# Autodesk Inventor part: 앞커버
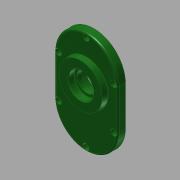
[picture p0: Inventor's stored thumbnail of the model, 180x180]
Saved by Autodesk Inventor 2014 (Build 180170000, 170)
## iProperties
Created: 2016-12
Part Number: 앞커버
Material: 일반
Document SubType Name: Modeling
Designer: mduedu
Density: 1 g/cm^3
Appearance: 매끄러움 - 짙은 산림 녹색
Mass: 97.7255 g
Surface Area: 264.104 cm^2
Volume: 97.7255 cm^3
Author: mduedu
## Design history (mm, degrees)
sketch "스케치1"
  geometry: L1 (40, -25)-(40, 25); L2 (-40, 25)-(-40, -25); L3 (-40, -25)-(40, 25); L4 (40, -25)-(-40, 25); A1 r 40 centre (0, 25) between (40, 25) and (-40, 25); A2 r 40 centre (0, -25) between (-40, -25) and (40, -25); 1 further point
  constraints: 8 end point, 4 point on circle, 4 tangent, 2 centre point, 2 midpoint, 1 parallel, 1 vertical
  dimensions: "d0" = 130 dimension on A2 A1; "d2" = 80 distance between parallel lines of L1 L2
extrude "돌출1" new body sketch "스케치1" distance "d3" = 10; taper "d4" = 0 deg
sketch "스케치2"
  geometry: C1 r 21 at (0, 11); 1 further point
  constraints: 1 centre point, 1 vertical alignment
  dimensions: "d5" = 42 diameter of C1; "d7" = 11 distance of C1.centre point (0, 0)
extrude "돌출2" join sketch "스케치2" distance "d8" = 7; taper "d9" = 0 deg
sketch "스케치3"
  geometry: C1 r 15 at (0, -33.1); C2 r 21 at (0, 11) reference; 1 further point
  constraints: 1 centre point, 1 vertical alignment
  dimensions: "d10" = 30 diameter of C1; "d71" = 44.1 distance of C1.centre C2.centre
extrude "돌출3" join sketch "스케치3" distance "d12" = 7; taper "d13" = 0 deg
sketch "스케치4"
  geometry: C1 r 28 at (0, 11); A1 r 21 centre (0, 11) between (8.978, -7.984) and (-8.978, -7.984) reference; 1 further point
  constraints: 1 centre point, 1 coincident
  dimensions: "d14" = 56 diameter of C1
extrude "돌출4" join sketch "스케치4" distance "d15" = 7; taper "d16" = -5 deg
hole "구멍1" diameter "d19" = 35; stored, may be unused: countersink angle "d23" = 90 deg, drill point angle "d25" = 0 deg; dims "d17" = 10, "d18" = 10, "d20" = 6, "d21" = 4, "d22" = 2, "d24" = 10
hole "구멍2" diameter "d28" = 22; stored, may be unused: countersink angle "d32" = 90 deg, drill point angle "d34" = 0 deg; dims "d26" = 10, "d27" = 10, "d29" = 6, "d30" = 4, "d31" = 2, "d33" = 7
hole "구멍3" diameter "d37" = 19; stored, may be unused: countersink angle "d41" = 90 deg, drill point angle "d43" = 0 deg; dims "d35" = 10, "d36" = 10, "d38" = 6, "d39" = 4, "d40" = 2, "d42" = 1
hole "구멍4" diameter "d46" = 32; stored, may be unused: countersink angle "d50" = 90 deg, drill point angle "d52" = 0 deg; dims "d44" = 10, "d45" = 10, "d47" = 6, "d48" = 4, "d49" = 2, "d51" = 8
hole "구멍5" diameter "d55" = 25; stored, may be unused: countersink angle "d59" = 90 deg, drill point angle "d61" = 0 deg; dims "d53" = 10, "d54" = 10, "d56" = 6, "d57" = 4, "d58" = 2, "d60" = 8
fillet "모깎기1" dims "d62" = 0.3
fillet "모깎기2" dims "d63" = 2
chamfer "모따기1" distance "d64" = 1; stored, may be unused: second distance "d65" = 2, angle "d66" = 45 deg
fillet "모깎기4" dims "d68" = 2
fillet "모깎기5" dims "d69" = 0.3
fillet "모깎기6" dims "d70" = 2
sketch "스케치5"
  geometry: L1 (-40, 25)-(-40, -25) reference; L2 (40, -25)-(40, 25) reference; L3 (35, 25)-(35, -25); L4 (-35, -25)-(-35, 25); A1 r 40 centre (0, 25) between (40, 25) and (-40, 25) reference; A2 r 40 centre (0, -25) between (-40, -25) and (40, -25) reference; A3 r 35 centre (0, 25) between (35, 25) and (-35, 25); A4 r 35 centre (0, -25) between (-35, -25) and (35, -25); 2 further points
  constraints: 5 point on circle, 4 end point, 2 centre point, 1 vertical alignment, 3 other
  dimensions: "d72" = 5 distance between parallel lines of L2 L3
sketch "스케치7"
  geometry: 1 further point
hole "구멍7" sketch "스케치7" at (0, 60) diameter "d80" = 4.5; stored, may be unused: countersink angle "d84" = 90 deg, drill point angle "d86" = 0 deg; dims "d81" = 6, "d82" = 8, "d83" = 4.6, "d85" = 8
node "솔리드1"
pattern_linear "직사각형 패턴1"
